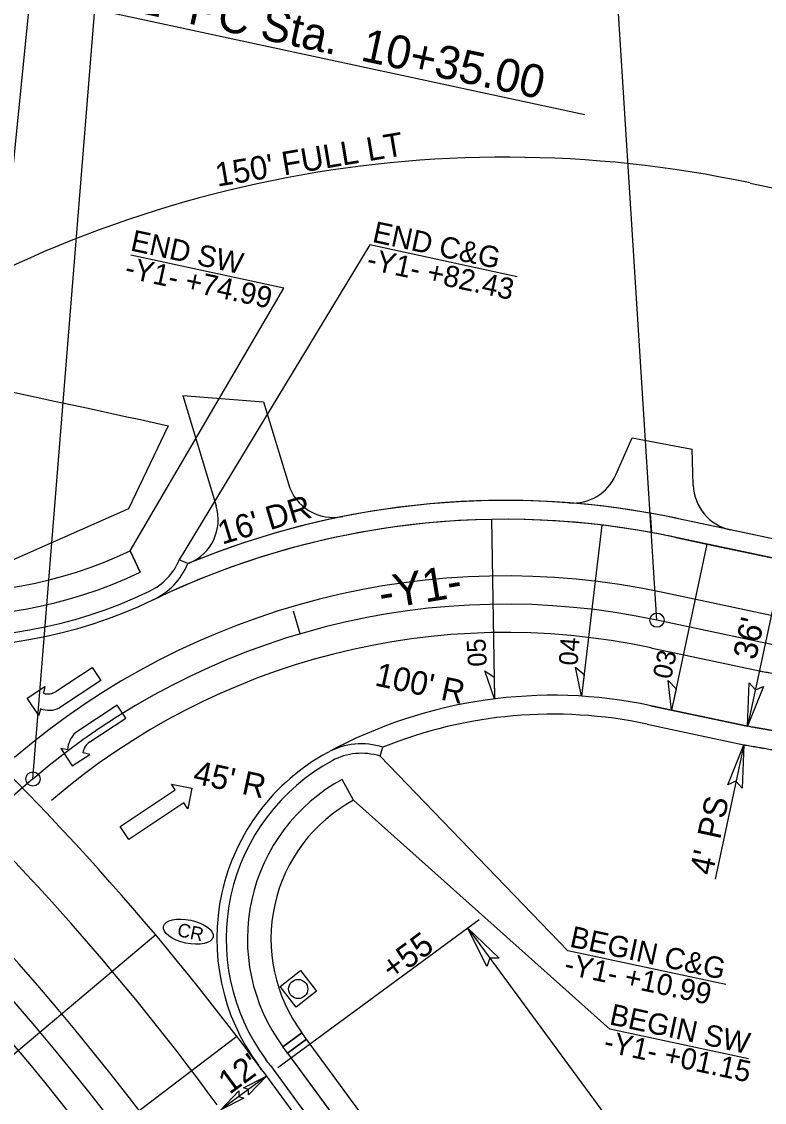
# Model space of a CAD drawing. Extents: x 1762196 to 1766326, y 709922 to 713142.
# Drawn here: x 1763337.1 to 1763494.7, y 712391.1 to 712620.3 of the extents above; entities that cross this region are included whole.
import ezdxf

# ---------------------------------------------------------------- set-up
doc = ezdxf.new("R2010")
doc.units = 0
for name, color, linetype in [('COGO Default Chain', 7, 'Continuous'), ('Default', 7, 'Continuous'), ('Old_Level_3', 7, 'Continuous'), ('Pattern 1', 7, 'Continuous'), ('Pattern 2', 7, 'Continuous'), ('Pattern 5', 7, 'Continuous'), ('Prop Conc 2ft 6in Curb and Gutter', 7, 'Continuous'), ('Prop Dimension', 7, 'Continuous'), ('Prop EOT', 7, 'Continuous'), ('Prop Horizontal Alignment', 7, 'Continuous'), ('Prop Horizontal Alignment Direction Label', 7, 'Continuous'), ('Prop Horizontal Alignment Station Label', 7, 'Continuous'), ('Prop Horizontal Alignment Tick Small', 7, 'Continuous'), ('Prop Lane Arrow CELL', 7, 'Continuous'), ('Prop Lane Lines', 7, 'Continuous'), ('Prop Paved Shoulder', 7, 'Continuous'), ('Prop Shade Medium', 7, 'Continuous'), ('Prop Superelevation  Arrow CELL', 7, 'Continuous'), ('Prop Superelevation Label', 7, 'Continuous'), ('Prop Terminator CELL', 7, 'Continuous')]:
    doc.layers.add(name, color=color, linetype=linetype)

msp = doc.modelspace()

# ---------------------------------------------------------------- linework, layer by layer
at = {"layer": 'COGO Default Chain'}
for points in [[(1763300.15, 712549.23), (1763314.78, 712546.01), (1763329.45, 712542.98), (1763344.08, 712539.74), (1763351.23, 712538.32)], [(1763351.23, 712538.32), (1763359.4, 712536.46), (1763361.68, 712535.99)], [(1763361.68, 712535.99), (1763368.2, 712534.57)], [(1763368.2, 712534.57), (1763359.78, 712516.93), (1763331.53, 712504.52)]]:
    msp.add_lwpolyline(points, dxfattribs=at)
at = {"layer": 'Default'}
msp.add_lwpolyline([(1763399.67, 712414.69), (1763395.31, 712411.29), (1763391.91, 712415.64), (1763396.26, 712419.05)], close=True, dxfattribs=at)
msp.add_circle((1763395.77, 712415.12), 2.03, dxfattribs=at)
at = {"layer": 'Old_Level_3'}
for p, q in [((1763371.27, 712541), (1763378.37, 712517.56)), ((1763371.27, 712541), (1763388.39, 712539.66)), ((1763388.39, 712539.66), (1763393.68, 712522.21)), ((1763463.14, 712524.13), (1763466.63, 712532.03)), ((1763466.63, 712532.03), (1763479.31, 712529.6)), ((1763479.55, 712521.96), (1763479.31, 712529.6))]:
    msp.add_line(p, q, dxfattribs=at)
for centre, start, end in [((1763453.99, 712528.17), 265.6023, 336.1435), ((1763403.25, 712525.11), 196.8633, 281.3099), ((1763489.55, 712522.28), 181.8082, 257.9589), ((1763368.8, 712514.66), 292.4168, 16.8633)]:
    msp.add_arc(centre, 10, start, end, dxfattribs=at)
at = {"layer": 'Pattern 1'}
for p, q in [((1763362.26, 712503.53), (1763360.09, 712508.04)), ((1763407.51, 712455.17), (1763405.12, 712459.57)), ((1763392.53, 712402.84), (1763396.55, 712405.81)), ((1763396.55, 712405.81), (1763392.53, 712402.84)), ((1763393.49, 712401.54), (1763397.52, 712404.5)), ((1763534.54, 712218.15), (1763397.52, 712404.5))]:
    msp.add_line(p, q, dxfattribs=at)
msp.add_lwpolyline([(1763397.52, 712404.5), (1763393.49, 712401.54), (1763530.51, 712215.18)], dxfattribs=at)
for centre, radius, start, end in [((1762933.05, 712063), 506.5, 36.325, 67.1495), ((1763321.68, 712587.77), 88.5, 233.4772, 295.722), ((1763321.68, 712587.77), 93.5, 233.4772, 295.722), ((1763423.49, 712425.73), 38.5, 118.4962, 216.487), ((1763423.49, 712425.73), 33.5, 118.4962, 216.487), ((1762933.05, 712063), 576.5, 36.32502, 36.48695), ((1762933.05, 712063), 576.5, 36.32502, 36.48695), ((1762933.05, 712063), 571.5, 36.325, 36.487), ((1762933.05, 712063), 571.5, 36.325, 36.487)]:
    msp.add_arc(centre, radius, start, end, dxfattribs=at)
at = {"layer": 'Pattern 2'}
for p, q in [((1763360.09, 712508.04), (1763362.26, 712503.53)), ((1763407.51, 712455.17), (1763405.12, 712459.57)), ((1763534.54, 712218.15), (1763397.52, 712404.5)), ((1763393.49, 712401.54), (1763530.51, 712215.18))]:
    msp.add_line(p, q, dxfattribs=at)
for centre, radius, start, end in [((1762933.05, 712063), 506.5, 36.325, 67.1495), ((1763321.68, 712587.77), 88.5, 233.4772, 295.722), ((1763321.68, 712587.77), 93.5, 233.4772, 295.722), ((1763423.49, 712425.73), 38.5, 118.4962, 216.487), ((1763423.49, 712425.73), 33.5, 118.4962, 216.487), ((1762933.05, 712063), 576.5, 36.32502, 36.48695), ((1762933.05, 712063), 571.5, 36.325, 36.487)]:
    msp.add_arc(centre, radius, start, end, dxfattribs=at)
at = {"layer": 'Pattern 5'}
msp.add_ellipse((1763372.44, 712427.28), major_axis=(5.26, -1.13), ratio=0.462467, dxfattribs=at)
at = {"layer": 'Prop Conc 2ft 6in Curb and Gutter'}
for p, q in [((1763372.38, 712505.32), (1763370.53, 712506.1)), ((1763413.12, 712464.48), (1763413.73, 712466.39)), ((1763389.87, 712398.87), (1763526.88, 712212.52))]:
    msp.add_line(p, q, dxfattribs=at)
for centre, radius, start, end in [((1762933.05, 712063), 511, 36.325, 65.7844), ((1763321.68, 712587.77), 98, 233.4772, 295.722), ((1763358.57, 712511.19), 13, 295.722, 336.9692), ((1763409.18, 712452.1), 13, 72.3285, 118.4962), ((1763423.49, 712425.73), 43, 118.4962, 216.487), ((1762933.05, 712063), 567, 36.325, 36.4998)]:
    msp.add_arc(centre, radius, start, end, dxfattribs=at)
at = {"layer": 'Prop Dimension'}
for p, q in [((1763491.63, 712586.03), (1763514.62, 712581.13)), ((1763410.94, 712572.89), (1763370.53, 712506.1)), ((1763442.2, 712566.17), (1763410.94, 712572.89)), ((1763392.69, 712563.75), (1763360.27, 712570.72)), ((1763360.09, 712508.04), (1763392.69, 712563.75)), ((1763498.61, 712506.03), (1763491.1, 712470.82)), ((1763490.26, 712466.91), (1763484.18, 712438.39)), ((1763452.99, 712423.23), (1763413.12, 712464.48)), ((1763407.51, 712455.17), (1763461.86, 712406.62)), ((1763434.15, 712429.81), (1763391.44, 712398.42)), ((1763431.73, 712428.03), (1763567.97, 712242.73)), ((1763486.45, 712416.04), (1763452.99, 712423.23)), ((1763491.29, 712400.29), (1763461.86, 712406.62)), ((1763389.03, 712396.64), (1763379.36, 712389.53))]:
    msp.add_line(p, q, dxfattribs=at)
msp.add_arc((1763439.73, 712342.72), 248.79, 77.9589, 125.0188, dxfattribs=at)
at = {"layer": 'Prop EOT'}
for p, q in [((1763498.61, 712506.03), (1763475.61, 712510.93)), ((1763470.59, 712475.2), (1763491.1, 712470.82)), ((1763388.26, 712397.69), (1763525.27, 712211.33))]:
    msp.add_line(p, q, dxfattribs=at)
for centre, radius, start, end in [((1762933.05, 712063), 513, 36.325, 65.7844), ((1763439.73, 712342.72), 172, 77.9589, 115.722), ((1763321.68, 712587.77), 100, 233.4772, 295.722), ((1763449.73, 712377.4), 100, 77.9589, 118.4962), ((1763423.49, 712425.73), 45, 118.4962, 216.487), ((1762933.05, 712063), 565, 36.325, 36.487)]:
    msp.add_arc(centre, radius, start, end, dxfattribs=at)
msp.add_spline([(1763540.41, 712462.35), (1763539.75, 712462.46), (1763539.08, 712462.58), (1763538.41, 712462.69), (1763537.75, 712462.8), (1763537.08, 712462.92), (1763536.41, 712463.03), (1763535.75, 712463.15), (1763535.08, 712463.26), (1763534.41, 712463.38), (1763533.75, 712463.49), (1763533.08, 712463.61), (1763532.42, 712463.72), (1763531.75, 712463.84), (1763531.08, 712463.95), (1763530.42, 712464.06), (1763529.75, 712464.18), (1763529.08, 712464.29), (1763528.42, 712464.41), (1763527.75, 712464.52), (1763527.08, 712464.64), (1763526.42, 712464.75), (1763525.75, 712464.87), (1763525.08, 712464.98), (1763524.42, 712465.1), (1763523.75, 712465.21), (1763523.09, 712465.32), (1763522.42, 712465.44), (1763521.75, 712465.55), (1763521.09, 712465.67), (1763520.42, 712465.78), (1763519.75, 712465.9), (1763519.09, 712466.01), (1763518.42, 712466.13), (1763517.75, 712466.24), (1763517.09, 712466.35), (1763516.42, 712466.47), (1763515.75, 712466.58), (1763515.09, 712466.7), (1763514.42, 712466.81), (1763513.76, 712466.93), (1763513.09, 712467.04), (1763512.42, 712467.16), (1763511.76, 712467.27), (1763511.09, 712467.39), (1763510.42, 712467.5), (1763509.76, 712467.61), (1763509.09, 712467.73), (1763508.42, 712467.84), (1763507.76, 712467.96), (1763507.09, 712468.07), (1763506.42, 712468.19), (1763505.76, 712468.3), (1763505.09, 712468.42), (1763504.42, 712468.53), (1763503.76, 712468.65), (1763503.09, 712468.76), (1763502.43, 712468.87), (1763501.76, 712468.99), (1763501.09, 712469.1), (1763500.43, 712469.22), (1763499.76, 712469.33), (1763499.09, 712469.45), (1763498.43, 712469.56), (1763497.76, 712469.68), (1763497.09, 712469.79), (1763496.43, 712469.91), (1763495.76, 712470.02), (1763495.09, 712470.13), (1763494.43, 712470.25), (1763493.76, 712470.36), (1763493.1, 712470.48), (1763492.43, 712470.59), (1763491.1, 712470.82)], degree=3, dxfattribs=at)
at = {"layer": 'Prop Horizontal Alignment'}
for p, q in [((1764408.68, 712293.5), (1763471.86, 712493.33)), ((1763339.51, 712459.65), (1763312.94, 712436.87))]:
    msp.add_line(p, q, dxfattribs=at)
for centre, radius, start, end in [((1762933.05, 712063), 533, 36.325, 77.7598), ((1763439.73, 712342.72), 154, 77.9589, 130.6003)]:
    msp.add_arc(centre, radius, start, end, dxfattribs=at)
at = {"layer": 'Prop Horizontal Alignment Station Label'}
for p, q in [((1763341.29, 712649.99), (1763320.6, 712443.44)), ((1763471.86, 712493.33), (1763462.61, 712639.04)), ((1763339.51, 712459.65), (1763352.65, 712622.89)), ((1763352.65, 712622.89), (1763456.54, 712600.55))]:
    msp.add_line(p, q, dxfattribs=at)
for centre in [(1763471.86, 712493.33), (1763339.51, 712459.65)]:
    msp.add_circle(centre, 1.5, dxfattribs=at)
at = {"layer": 'Prop Horizontal Alignment Tick Small'}
msp.add_line((1763396.21, 712490.44), (1763394.79, 712495.24), dxfattribs=at)
at = {"layer": 'Prop Lane Arrow CELL'}
for p, q in [((1763344.45, 712478.26), (1763352.07, 712483.32)), ((1763352.07, 712483.32), (1763353.89, 712480.57)), ((1763353.89, 712480.57), (1763345.1, 712474.73)), ((1763338.3, 712476.76), (1763342.02, 712479.29)), ((1763342.02, 712479.29), (1763341.73, 712477.83)), ((1763340.77, 712473.12), (1763338.3, 712476.76)), ((1763341.07, 712474.58), (1763340.77, 712473.12)), ((1763357.37, 712475.32), (1763348.58, 712469.49)), ((1763359.2, 712472.57), (1763357.37, 712475.32)), ((1763351.57, 712467.52), (1763359.2, 712472.57)), ((1763346.87, 712465.83), (1763345.41, 712466.13)), ((1763345.41, 712466.13), (1763347.8, 712462.43)), ((1763347.8, 712462.43), (1763351.58, 712464.88)), ((1763351.58, 712464.88), (1763350.12, 712465.18)), ((1763369.69, 712457.32), (1763368.86, 712458.57)), ((1763368.86, 712458.57), (1763373.2, 712457.73)), ((1763373.2, 712457.73), (1763372.34, 712453.32)), ((1763358.02, 712449.58), (1763369.69, 712457.32)), ((1763371.51, 712454.57), (1763359.85, 712446.83)), ((1763372.34, 712453.32), (1763371.51, 712454.57)), ((1763359.85, 712446.83), (1763358.02, 712449.58))]:
    msp.add_line(p, q, dxfattribs=at)
for centre, radius, start, end in [((1763342.64, 712480.97), 3.28, 253.8996, 303.5578), ((1763342.9, 712479.48), 5.25, 249.57, 294.8817), ((1763352.1, 712465.62), 5.25, 132.2338, 177.5455), ((1763353.36, 712464.79), 3.28, 123.5578, 173.216)]:
    msp.add_arc(centre, radius, start, end, dxfattribs=at)
at = {"layer": 'Prop Lane Lines'}
for p, q in [((1763496.1, 712494.29), (1763473.11, 712499.2)), ((1763470.6, 712487.46), (1763493.6, 712482.56))]:
    msp.add_line(p, q, dxfattribs=at)
for centre, radius, start, end in [((1762933.05, 712063), 539, 36.325, 77.7598), ((1762933.05, 712063), 527, 36.325, 77.7598), ((1763439.73, 712342.72), 160, 77.9589, 130.6003), ((1763439.73, 712342.72), 148, 77.9589, 130.6003), ((1762933.05, 712063), 565, 36.325, 48.2811), ((1762933.05, 712063), 553, 36.325, 48.0096)]:
    msp.add_arc(centre, radius, start, end, dxfattribs=at)
msp.add_spline([(1763493.6, 712482.56), (1763494.27, 712482.44), (1763494.93, 712482.33), (1763495.6, 712482.21), (1763496.27, 712482.1), (1763496.93, 712481.98), (1763497.6, 712481.87), (1763498.26, 712481.76), (1763498.93, 712481.64), (1763499.6, 712481.53), (1763500.26, 712481.41), (1763500.93, 712481.3), (1763501.6, 712481.18), (1763502.26, 712481.07), (1763502.93, 712480.95), (1763503.6, 712480.84), (1763504.26, 712480.72), (1763504.93, 712480.61), (1763505.6, 712480.5), (1763506.26, 712480.38), (1763506.93, 712480.27), (1763507.59, 712480.15), (1763508.26, 712480.04), (1763508.93, 712479.92), (1763509.59, 712479.81), (1763510.26, 712479.69), (1763510.93, 712479.58), (1763511.59, 712479.47), (1763512.26, 712479.35), (1763512.93, 712479.24), (1763513.59, 712479.12), (1763514.26, 712479.01), (1763514.93, 712478.89), (1763515.59, 712478.78), (1763516.26, 712478.66), (1763516.92, 712478.55), (1763517.59, 712478.43), (1763518.26, 712478.32), (1763518.92, 712478.21), (1763519.59, 712478.09), (1763520.26, 712477.98), (1763520.92, 712477.86), (1763521.59, 712477.75), (1763522.26, 712477.63), (1763522.92, 712477.52), (1763523.59, 712477.4), (1763524.26, 712477.29), (1763524.92, 712477.17), (1763525.59, 712477.06), (1763526.26, 712476.95), (1763526.92, 712476.83), (1763527.59, 712476.72), (1763528.25, 712476.6), (1763528.92, 712476.49), (1763529.59, 712476.37), (1763530.25, 712476.26), (1763530.92, 712476.14), (1763531.59, 712476.03), (1763532.25, 712475.91), (1763532.92, 712475.8), (1763533.59, 712475.69), (1763534.25, 712475.57), (1763534.92, 712475.46), (1763535.59, 712475.34), (1763536.25, 712475.23), (1763536.92, 712475.11), (1763537.58, 712475), (1763538.25, 712474.88), (1763538.92, 712474.77), (1763539.58, 712474.66), (1763540.25, 712474.54), (1763540.92, 712474.43), (1763541.58, 712474.31), (1763542.25, 712474.2), (1763542.92, 712474.08)], degree=3, dxfattribs=at)
at = {"layer": 'Prop Paved Shoulder'}
for p, q in [((1763499.44, 712509.94), (1763476.45, 712514.85)), ((1763469.76, 712471.28), (1763490.26, 712466.91))]:
    msp.add_line(p, q, dxfattribs=at)
for centre, radius, start, end in [((1763439.73, 712342.72), 176, 77.9589, 112.5007), ((1763358.57, 712511.19), 15, 295.722, 336.9692), ((1763449.73, 712377.4), 96, 77.9589, 112.0244), ((1763409.18, 712452.1), 15, 72.3285, 118.4962)]:
    msp.add_arc(centre, radius, start, end, dxfattribs=at)
msp.add_spline([(1763490.26, 712466.91), (1763490.93, 712466.79), (1763491.59, 712466.68), (1763492.26, 712466.57), (1763492.93, 712466.45), (1763493.59, 712466.34), (1763494.26, 712466.22), (1763494.93, 712466.11), (1763495.59, 712465.99), (1763496.26, 712465.88), (1763496.93, 712465.76), (1763497.59, 712465.65), (1763498.26, 712465.53), (1763498.93, 712465.42), (1763499.59, 712465.31), (1763500.26, 712465.19), (1763500.92, 712465.08), (1763501.59, 712464.96), (1763502.26, 712464.85), (1763502.92, 712464.73), (1763503.59, 712464.62), (1763504.26, 712464.5), (1763504.92, 712464.39), (1763505.59, 712464.28), (1763506.26, 712464.16), (1763506.92, 712464.05), (1763507.59, 712463.93), (1763508.26, 712463.82), (1763508.92, 712463.7), (1763509.59, 712463.59), (1763510.25, 712463.47), (1763510.92, 712463.36), (1763511.59, 712463.24), (1763512.25, 712463.13), (1763512.92, 712463.02), (1763513.59, 712462.9), (1763514.25, 712462.79), (1763514.92, 712462.67), (1763515.59, 712462.56), (1763516.25, 712462.44), (1763516.92, 712462.33), (1763517.59, 712462.21), (1763518.25, 712462.1), (1763518.92, 712461.98), (1763519.59, 712461.87), (1763520.25, 712461.76), (1763520.92, 712461.64), (1763521.58, 712461.53), (1763522.25, 712461.41), (1763522.92, 712461.3), (1763523.58, 712461.18), (1763524.25, 712461.07), (1763524.92, 712460.95), (1763525.58, 712460.84), (1763526.25, 712460.73), (1763526.92, 712460.61), (1763527.58, 712460.5), (1763528.25, 712460.38), (1763528.92, 712460.27), (1763529.58, 712460.15), (1763530.25, 712460.04), (1763530.91, 712459.92), (1763531.58, 712459.81), (1763532.25, 712459.69), (1763532.91, 712459.58), (1763533.58, 712459.47), (1763534.25, 712459.35), (1763534.91, 712459.24), (1763535.58, 712459.12), (1763536.25, 712459.01), (1763536.91, 712458.89), (1763537.58, 712458.78), (1763538.25, 712458.66), (1763538.91, 712458.55), (1763539.58, 712458.43)], degree=3, dxfattribs=at)
at = {"layer": 'Prop Shade Medium'}
for p, q in [((1763470.68, 712511.91), (1763470.42, 712516.02)), ((1763470.42, 712516.02), (1763470.68, 712511.91)), ((1763469.76, 712471.28), (1763490.26, 712466.91))]:
    msp.add_line(p, q, dxfattribs=at)
for points in [[(1763499.44, 712509.94), (1763487.46, 712512.5), (1763476.45, 712514.85)], [(1763475.61, 712510.93), (1763482.46, 712509.47), (1763498.61, 712506.03)], [(1763491.1, 712470.82), (1763474.95, 712474.27), (1763470.59, 712475.2)]]:
    msp.add_lwpolyline(points, dxfattribs=at)
for centre, radius, start, end in [((1763439.73, 712342.72), 176, 79.9589, 112.5007), ((1763439.73, 712342.72), 176, 77.9589, 79.9589), ((1763439.73, 712342.72), 172, 79.6346, 115.722), ((1763439.73, 712342.72), 172, 77.9589, 79.6346), ((1763358.57, 712511.19), 15, 295.722, 336.9692), ((1763449.73, 712377.4), 100, 77.9589, 118.4962), ((1763449.73, 712377.4), 96, 77.9589, 112.0244), ((1763409.18, 712452.1), 15, 72.3285, 118.4962)]:
    msp.add_arc(centre, radius, start, end, dxfattribs=at)
msp.add_open_spline([(1763507.53, 712468), (1763507.39, 712468.02), (1763507.24, 712468.05), (1763507.09, 712468.07), (1763506.87, 712468.11), (1763506.65, 712468.15), (1763506.42, 712468.19), (1763506.2, 712468.23), (1763505.98, 712468.26), (1763505.76, 712468.3), (1763505.54, 712468.34), (1763505.31, 712468.38), (1763505.09, 712468.42), (1763504.87, 712468.45), (1763504.65, 712468.49), (1763504.42, 712468.53), (1763504.2, 712468.57), (1763503.98, 712468.61), (1763503.76, 712468.65), (1763503.54, 712468.68), (1763503.31, 712468.72), (1763503.09, 712468.76), (1763502.87, 712468.8), (1763502.65, 712468.84), (1763502.43, 712468.87), (1763502.2, 712468.91), (1763501.98, 712468.95), (1763501.76, 712468.99), (1763501.54, 712469.03), (1763501.31, 712469.07), (1763501.09, 712469.1), (1763500.87, 712469.14), (1763500.65, 712469.18), (1763500.43, 712469.22), (1763500.2, 712469.26), (1763499.98, 712469.29), (1763499.76, 712469.33), (1763499.54, 712469.37), (1763499.32, 712469.41), (1763499.09, 712469.45), (1763498.87, 712469.49), (1763498.65, 712469.52), (1763498.43, 712469.56), (1763498.2, 712469.6), (1763497.98, 712469.64), (1763497.76, 712469.68), (1763497.54, 712469.71), (1763497.32, 712469.75), (1763497.09, 712469.79), (1763496.87, 712469.83), (1763496.65, 712469.87), (1763496.43, 712469.91), (1763496.21, 712469.94), (1763495.98, 712469.98), (1763495.76, 712470.02), (1763495.54, 712470.06), (1763495.32, 712470.1), (1763495.09, 712470.13), (1763494.87, 712470.17), (1763494.65, 712470.21), (1763494.43, 712470.25), (1763494.21, 712470.29), (1763493.98, 712470.32), (1763493.76, 712470.36), (1763493.54, 712470.4), (1763493.32, 712470.44), (1763493.1, 712470.48), (1763492.87, 712470.52), (1763492.65, 712470.55), (1763492.43, 712470.59), (1763491.98, 712470.67), (1763491.54, 712470.74), (1763491.1, 712470.82)], degree=3, dxfattribs=at)
msp.add_spline([(1763490.26, 712466.91), (1763490.93, 712466.79), (1763491.59, 712466.68), (1763492.26, 712466.57), (1763492.93, 712466.45), (1763493.59, 712466.34), (1763494.26, 712466.22), (1763494.93, 712466.11), (1763495.59, 712465.99), (1763496.26, 712465.88), (1763496.93, 712465.76), (1763497.59, 712465.65), (1763498.26, 712465.53), (1763498.93, 712465.42), (1763499.59, 712465.31), (1763500.26, 712465.19), (1763500.92, 712465.08), (1763501.59, 712464.96), (1763502.26, 712464.85), (1763502.92, 712464.73), (1763503.59, 712464.62), (1763504.26, 712464.5), (1763504.92, 712464.39), (1763505.59, 712464.28), (1763506.26, 712464.16), (1763506.7, 712464.08)], degree=3, dxfattribs=at)
at = {"layer": 'Prop Superelevation  Arrow CELL'}
for points in [[(1763455.85, 712477.21), (1763454.57, 712483.4), (1763456.4, 712481.8)], [(1763437.44, 712476.64), (1763435.34, 712482.6), (1763437.36, 712481.26)], [(1763474.95, 712474.27), (1763474.24, 712480.55), (1763475.91, 712478.79)]]:
    msp.add_lwpolyline(points, close=True, dxfattribs=at)
at = {"layer": 'Prop Superelevation Label'}
for p, q in [((1763436.79, 712514.69), (1763437.44, 712476.64)), ((1763460.19, 712513.5), (1763455.85, 712477.21)), ((1763482.46, 712509.47), (1763474.95, 712474.27)), ((1763365.54, 712426.57), (1763325.74, 712393.11)), ((1763382.75, 712405.05), (1763341.37, 712373.57))]:
    msp.add_line(p, q, dxfattribs=at)
at = {"layer": 'Prop Terminator CELL'}
for points in [[(1763494.49, 712479.3), (1763491.1, 712470.82), (1763491.42, 712480.01), (1763492.74, 712478.55)], [(1763486.87, 712458.43), (1763490.26, 712466.91), (1763489.94, 712457.72), (1763488.61, 712459.18)], [(1763435.81, 712419.86), (1763431.73, 712428.03), (1763438.38, 712421.69), (1763436.41, 712421.67)], [(1763384.13, 712394.19), (1763389.03, 712396.64), (1763385.22, 712392.65), (1763385.21, 712393.83)], [(1763384.26, 712391.98), (1763379.36, 712389.53), (1763383.17, 712393.52), (1763383.18, 712392.34)]]:
    msp.add_lwpolyline(points, close=True, dxfattribs=at)

# ---------------------------------------------------------------- texts
at = {"layer": 'Pattern 5'}
msp.add_text('CR', height=2.88, rotation=347.8639, dxfattribs=at).set_placement((1763369.93, 712426.37))
at = {"layer": 'Prop Dimension'}
for s, height, rotation, p in [("150' FULL LT", 5, 9.5674, (1763378.62, 712585.24)), ('END C&G', 4.5, 347.8639, (1763411.3, 712573.57)), ('END SW', 4.5, 347.8639, (1763359.99, 712571.75)), ('-Y1- +74.99', 4.5, 347.8639, (1763358.76, 712566.03)), ('-Y1- +82.43', 4.5, 347.8639, (1763410.07, 712567.85)), ("16' DR", 5, 16.8633, (1763379.63, 712509.32)), ("36'", 5, 77.9589, (1763492.85, 712484.73)), ("100' R", 5, 347.8639, (1763411.81, 712479.52)), ("45' R", 5, 347.8639, (1763373.24, 712458.76)), ('PS', 5, 77.828, (1763485.27, 712446.65)), ("4' ", 5, 77.828, (1763483.63, 712439.03)), ('BEGIN C&G', 4.5, 347.8639, (1763453.17, 712424.12)), ('+55', 5, 36.325, (1763415.78, 712416.8)), ('-Y1- +10.99', 4.5, 347.8639, (1763451.94, 712418.4)), ('BEGIN SW', 4.5, 347.8639, (1763461.58, 712407.65)), ('-Y1- +01.15', 4.5, 347.8639, (1763460.35, 712401.93)), ("12'", 5, 36.325, (1763381.21, 712392.64))]:
    msp.add_text(s, height=height, rotation=rotation, dxfattribs=at).set_placement(p)
at = {"layer": 'Prop Horizontal Alignment Direction Label'}
msp.add_text('-Y1- ', height=7, rotation=9.3733, dxfattribs=at).set_placement((1763413.42, 712495.53))
at = {"layer": 'Prop Horizontal Alignment Station Label'}
msp.add_text('-Y1- PC Sta.  10+35.00', height=7, rotation=347.8638, dxfattribs=at).set_placement((1763352.33, 712624.19))
at = {"layer": 'Prop Superelevation Label'}
for s, rotation, p in [('05', 93.5832, (1763435.82, 712483.6)), ('04', 85.7702, (1763455.01, 712483.6)), ('03', 77.9589, (1763474.84, 712480.64))]:
    msp.add_text(s, height=4, rotation=rotation, dxfattribs=at).set_placement(p)

doc.saveas('drawing.dxf')
